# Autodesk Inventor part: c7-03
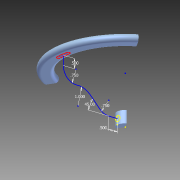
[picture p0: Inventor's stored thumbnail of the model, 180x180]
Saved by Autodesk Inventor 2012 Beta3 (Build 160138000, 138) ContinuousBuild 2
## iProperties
Created: 2010-12
Part Number: c7-03
Document SubType Name: Modeling
Designer: Thom Tremblay
Density: 1 g/cm^3
Material: Default
Author: Thom Tremblay
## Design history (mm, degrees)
sketch "Sketch2"
  geometry: L1 (0, 0)-(-11.43, 0); L2 (-11.43, 0)-(-11.43, 16.51); L3 (-11.43, 16.51)-(0, 16.51); L4 (0, 16.51)-(0, 0); L5 (-96.52, 66.04)-(-86.36, 66.04); L6 (-86.36, 76.2)-(-96.52, 76.2); L7 (-95.25, 74.93)-(-87.63, 74.93); L8 (-96.52, 76.2)-(-95.25, 74.93); L9 (-86.36, 76.2)-(-87.63, 74.93); A1 r 5.08 centre (-86.36, 71.12) between (-86.36, 66.04) and (-86.36, 76.2); A2 r 5.08 centre (-96.52, 71.12) between (-96.52, 76.2) and (-96.52, 66.04)
  constraints: 18 end point, 4 parallel, 4 point on circle, 4 tangent, 2 centre point, 2 horizontal, 2 perpendicular
  dimensions: "d6" = 16.51 distance of L1.end L2.end; "d7" = 22.86 diameter of L2 L4; "d10" = 5.08 radius of A1; "d11" = 20.32 dimension on A2 A1; "d12" = 3.81 distance from line of A1.centre L7; "d13" = 7.62 distance of L7.start L7.end; "d14" = 76.2 distance from line of L6.end L1; "d15" = 203.2 dimension on A2 L4
revolve "Revolution1" sketch "Sketch2" stored, may be unused: angle "d16" = 120 deg
sketch "Loft Sketch 1"
  geometry: L1 (-91.007, -8.89)-(-91.007, 8.89); A1 r 88.9 centre (0, 0) between (-88.479, 8.643) and (-88.479, -8.643); A2 r 93.98 centre (0, 0) between (-93.535, 9.137) and (-93.535, -9.137); A3 r 2.54 centre (-91.007, -8.89) between (-93.535, -9.137) and (-88.479, -8.643); A4 r 2.54 centre (-91.007, 8.89) between (-88.479, 8.643) and (-93.535, 9.137); 2 further points
  constraints: 8 point on circle, 4 centre point, 4 tangent, 2 end point, 1 coincident, 1 midpoint, 1 vertical
  dimensions: "d17" = 17.78 distance of L1.start L1.end; "d18" = 88.9 radius of A1; "d19" = 5.08 diameter of A4
sketch "Loft Sketch 2"
  node "Project from Sketch4"
sketch "Sketch10"
  geometry: L1 (-11.43, 7.62)-(-24.13, 7.62); L2 (-37.6, 13.2)-(-51.331, 26.93); L3 (-91.007, 53.34)-(-91.007, 66.04); A1 r 19.05 centre (-24.13, 26.67) between (-37.6, 13.2) and (-24.13, 7.62); A2 r 25.4 centre (-69.292, 8.97) between (-51.331, 26.93) and (-70.815, 34.324); A3 r 19.05 centre (-71.957, 53.34) between (-91.007, 53.34) and (-70.815, 34.324); 1 further point
  constraints: 6 end point, 6 point on circle, 5 tangent, 3 centre point, 1 horizontal, 1 perpendicular
  dimensions: "d65" = 12.7 distance of L1.start L1.end; "d66" = 19.05 radius of A1; "d67" = 19.05 radius of A3; "d68" = 12.7 distance of L3.start L3.end; "d69" = 25.4 radius of A2; "d70" = 45 deg angle of L1 L2
pattern_circular "Circular Pattern2" dims "d72" = 360 deg
body "Solid1"
sketch "Sketch4"
  geometry: C1 r 3.81 at (0, 7.62); 1 further point
  constraints: 1 centre point, 1 vertical alignment
  dimensions: "d63" = 7.62 diameter of C1; "d64" = 7.62 distance of point (0, 0) C1.centre
